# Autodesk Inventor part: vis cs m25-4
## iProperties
Author: chr
Shininess: 20.0
Angle Display Precision: 2
Document Length Units: 11269
Document Angle Units: 11283
Document Time Units: 11279
Document Mass Units: 11290
Document Length Units Precision: 3
Document Angle Units Precision: 2
Compacted: False
PropertySet Name: _Private Model Information
Created: 2002-03
Part Number: vis cs m25-4
Material: Par défaut
Document SubType Name: Modélisation
Designer: chr
Control State: 0
Master: False
Checked Out: False
PropertySet Name: Design Tracking Control
Density: 0.0
Volumn: 0.0
Area: 0.0
PropertySet Name: Model Information
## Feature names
1. Base1
